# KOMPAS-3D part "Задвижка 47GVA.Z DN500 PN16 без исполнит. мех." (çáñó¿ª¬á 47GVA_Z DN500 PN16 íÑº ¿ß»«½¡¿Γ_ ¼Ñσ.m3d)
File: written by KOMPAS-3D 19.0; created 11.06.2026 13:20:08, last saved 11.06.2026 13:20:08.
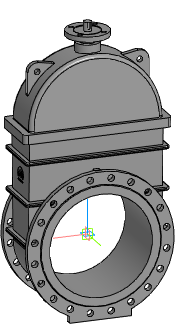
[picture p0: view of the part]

Document properties: Автор: Евгений; Полное имя файла: Z:\3.Личные\kachalov\001_3d для проектировщиков\2.2 Тип 47GVA, 47GVA.Z\_stp\_stp_Задвижка 47GVA.Z DN350-DN1200 без исп.мех\Задвижка 47GVA_Z DN500 PN16 без исполнит_ мех.m3d

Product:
- Part/product: Задвижка 47GVA.Z DN500 PN16 без исполнит. мех.

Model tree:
1. Операция без истории:1  (labels: Задвижка 47GVA.Z DN500 PN16 без исполнит. мех.)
